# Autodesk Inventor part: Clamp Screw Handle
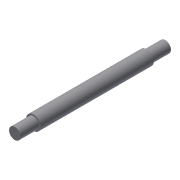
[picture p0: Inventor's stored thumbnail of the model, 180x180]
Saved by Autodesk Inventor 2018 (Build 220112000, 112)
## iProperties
Shininess: 77.0
Length Units: 11269
Angle Units: 11279
Time Units: 11290
Mass Units: 11283
Length Display Precision: 3
Angle Display Precision: 2
Compacted: True
Created: 2002-02
Part Number: Clamp Screw Handle
Document SubType Name: Modeling
Designer: ***
Density: 1 g/cm^3
Material: Generic
Mass: 7.51155 g
Surface Area: 32.9239 cm^2
Volume: 7.51155 cm^3
Appearance: Default
Density: 0.0
Volumn: 0.0
Area: 0.0
PropertySet Name: Model Information
Control State: 0
Master: False
Checked Out: False
Author: ***
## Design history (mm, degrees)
sketch "Sketch1"
  geometry: L1 (0, 105)-(4, 105); L2 (4, 105)-(4, 92); L3 (4, 92)-(5, 92); L4 (5, 92)-(5, 13); L5 (5, 13)-(4, 13); L6 (4, 13)-(4, 0); L7 (4, 0)-(0, 0); L8 (0, 0)-(0, 105)
  constraints: 16 end point, 5 parallel, 2 equal length, 1 collinear, 1 horizontal, 1 perpendicular
  dimensions: "d0" = 10 diameter of L4 L8; "d1" = 8 diameter of L2 L8; "d2" = 13 distance of L1.end L2.end; "d3" = 79 distance of L3.end L4.end
revolve "Revolution1" sketch "Sketch1" stored, may be unused: angle "d4" = 90 deg
body "Solid1"
